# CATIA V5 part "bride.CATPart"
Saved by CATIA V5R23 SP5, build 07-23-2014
Part number: bride
Bounding box of the stored display mesh (mm): x 0 to 16, y -92.5 to 92.5, z -92.5 to 92.5
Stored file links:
  C:\wamp\www\COURS\CONCEPTION GMP1\TITRE 01-CATIA VOLUMIQUE\05--ACTIONNEUR DE VANNE\prof\CORRECTION\Assemblage\bride.CATPart
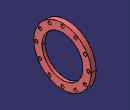
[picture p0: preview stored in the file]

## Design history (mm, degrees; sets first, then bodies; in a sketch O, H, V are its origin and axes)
Body1 (main body)
  Sketch1 on yz-plane, origin (0, 0, 0), H (0, 1, 0), V (0, 0, 1)
    circle A1 centre (0, 0) radius 92.5
    circle A2 centre (0, 0) radius 66
    radius A2 = 66
    radius A1 = 92.5
  Pad1: profile Sketch1, direction (1, 0, 0), length 16
  Sketch2 on start face of Pad1, origin (0, 0, 0), H (0, -1, 0), V (0, 0, 1)
    circle A1 centre (0, 0) radius 76
    radius A1 = 76
  Pocket1: profile Sketch2, direction (1, 0, 0), length 6
  Sketch3 on end face of Pad1, origin (16, -34.1953, 70.1269), H (0, 1, 0), V (0, 0, 1)
    point P1 (34.1953, 13.8731)
    reference intersected line E1 through (34.1953, 0) direction (0, 1) from zx-plane
    reference intersected line E2 through (0, -70.1269) direction (-1, 0) from xy-plane
    distance P1 E2 = 84
    coincidence: P1 E1
  Hole1: placed by Sketch3, at (16, 0, 84) direction (-1, 0, 0), diameter 10.5, through (limit type 3)
  CircPattern1: of Hole1, instances 12, angular step 30 {= 360.0*1 deg/CircPattern1.AngularNumber}, axis from face of Pad1 from Sketch1.A2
